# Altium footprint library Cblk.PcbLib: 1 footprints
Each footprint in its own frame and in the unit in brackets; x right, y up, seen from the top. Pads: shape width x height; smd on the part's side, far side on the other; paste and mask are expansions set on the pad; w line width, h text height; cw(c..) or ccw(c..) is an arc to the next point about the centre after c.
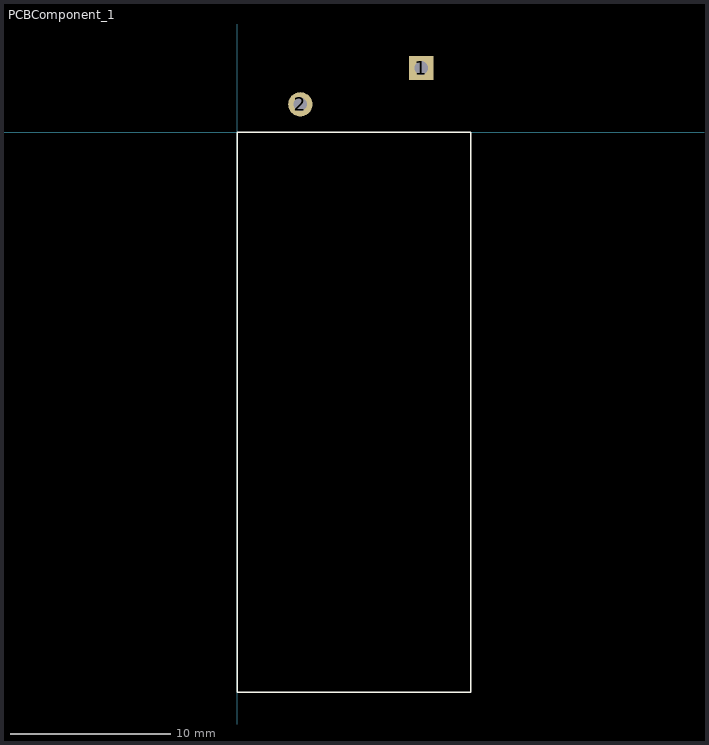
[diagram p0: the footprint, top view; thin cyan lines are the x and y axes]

## PCBComponent_1 [mm]
pads (2):
  rect 1.524x1.524 hole 0.85: 1(11.5,4.025)
  round 1.524 hole 0.85: 2(3.95,1.75)
Top Overlay:
  lines w0.1: 0,-35 0,0 14.6,0 14.6,-35 0,-35
M5 Assembly Top:
  text ".Designator" at -2,-0.7 h1.85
